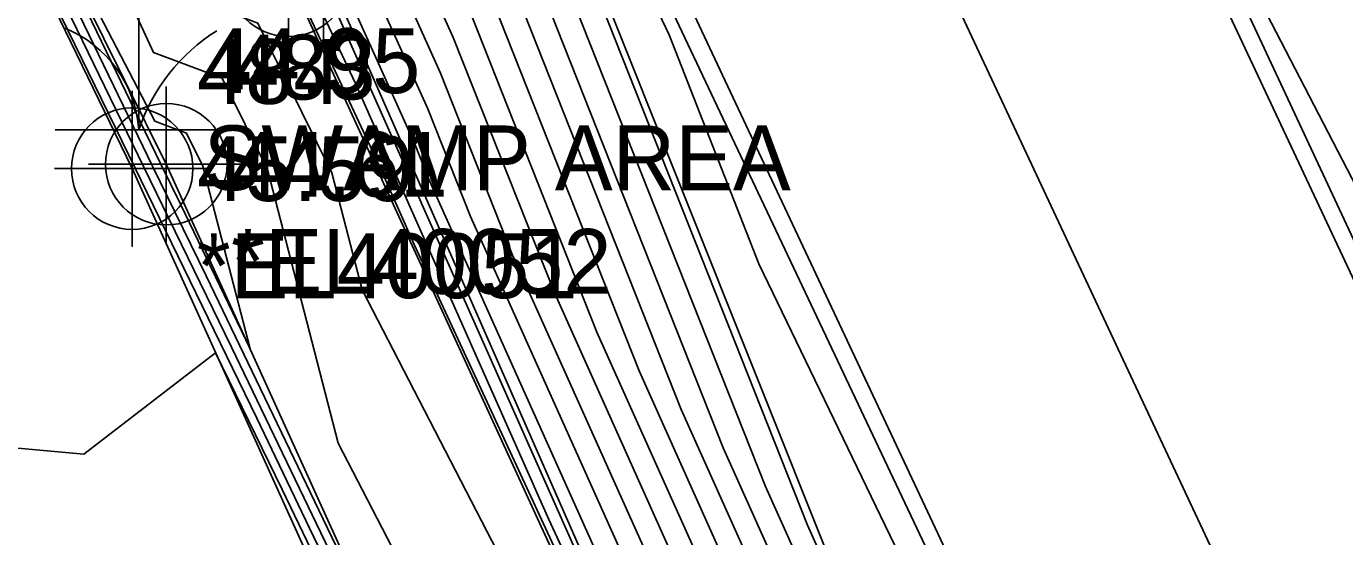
# Model space of a CAD drawing. Extents: x 2090860 to 2091277, y 159470 to 160080.
# Drawn here: x 2090993 to 2091043.8, y 159814.9 to 159834.6 of the extents above; entities that cross this region are included whole.
import ezdxf

# ---------------------------------------------------------------- set-up
doc = ezdxf.new("R2010")
doc.units = 0
for name, color, linetype in [('DTM Contours Major', 7, 'Continuous'), ('DTM Contours Minor', 7, 'Continuous'), ('Exist DTM Breakline', 7, 'Continuous'), ('Exist DTM Breakline Cogo Comment', 7, 'Continuous'), ('Exist DTM Breakline Cogo Elevation', 7, 'Continuous'), ('Exist DTM Breakline Cogo Number', 7, 'Continuous'), ('Exist DTM Breakline Cogo Point CELL', 7, 'Continuous'), ('Exist DTM Crownline', 7, 'Continuous'), ('Exist Hydro Swamp or Marsh', 7, 'Continuous'), ('Exist Hydro Swamp or Marsh Cogo Comment', 7, 'Continuous'), ('Exist Hydro Swamp or Marsh Cogo Elevation', 7, 'Continuous'), ('Exist Roads EOP', 7, 'Continuous'), ('Exist Roads EOT', 7, 'Continuous')]:
    doc.layers.add(name, color=color, linetype=linetype)

msp = doc.modelspace()

# ---------------------------------------------------------------- linework, layer by layer
at = {"layer": 'DTM Contours Major'}
for points in [[(2090991.853, 159864.196), (2090992.701, 159862.198), (2091004.114, 159836.848), (2091004.895, 159835.174), (2091007.518, 159829.269), (2091018.331, 159804.925), (2091019.741, 159801.878), (2091021.206, 159801.236), (2091025.093, 159800.189), (2091028.857, 159799.035), (2091029.349, 159799.339), (2091029.689, 159799.398), (2091044.087, 159806.371), (2091055.495, 159811.774), (2091056.395, 159812.282), (2091061.025, 159819.665), (2091060.533, 159819.671), (2091060.876, 159820.18), (2091051.784, 159837.119), (2091046.749, 159846.634), (2091042.53, 159854.466), (2091040.766, 159857.8), (2091031.335, 159877.368)], [(2091016.707, 159800.202), (2091008.385, 159811.907), (2091004.989, 159818.475), (2091002.257, 159829.041), (2091000.514, 159832.567), (2090997.856, 159833.556), (2090989.841, 159850.886), (2090987.897, 159859.839), (2090982.037, 159867.754), (2090974.898, 159876.535), (2090983.754, 159858.196), (2090986.806, 159851.928), (2090996.121, 159832.681), (2090997.829, 159829.173), (2090999.89, 159824.931), (2091004.415, 159815.535), (2091007.296, 159809.554), (2091015.202, 159792.842), (2091016.707, 159800.202)], [(2091011.396, 159839.656), (2091019.854, 159818.29), (2091022.735, 159811.87), (2091023.309, 159811.188), (2091027.181, 159801.43), (2091026.345, 159800.929), (2091025.775, 159800.251), (2091027.452, 159799.737), (2091029.469, 159800.98), (2091029.973, 159801.069), (2091031.587, 159801.932), (2091031.862, 159802.058), (2091035.483, 159803.649), (2091049.261, 159810.176)], [(2091007.255, 159838.974), (2091009.433, 159834.136), (2091013.348, 159824.247), (2091021.218, 159806.708), (2091022.786, 159804.845), (2091024.237, 159801.19), (2091023.923, 159801.002), (2091023.71, 159800.748), (2091028.154, 159799.386), (2091029.409, 159800.16), (2091030.276, 159800.311), (2091033.292, 159801.772), (2091055.189, 159812.142), (2091056.917, 159813.118), (2091059.879, 159817.842), (2091059.097, 159817.852), (2091058.757, 159817.756), (2091058.394, 159817.711), (2091056.078, 159816.651), (2091046.739, 159834.797)]]:
    msp.add_lwpolyline(points, dxfattribs=at)
at = {"layer": 'DTM Contours Minor'}
for points in [[(2090953.056, 159921.956), (2090965.045, 159895.337), (2090965.357, 159894.662), (2090965.917, 159893.402), (2090966.117, 159891.569), (2090966.399, 159891.209), (2090966.744, 159891.353), (2090970.598, 159883.648), (2090979.253, 159865.886), (2090979.998, 159864.343), (2090992.069, 159839.553), (2090993.271, 159837.069), (2090997.157, 159829.086), (2091001.847, 159819.434), (2091003.887, 159815.198), (2091014.815, 159792.51), (2091016.869, 159788.257), (2091017.431, 159786.838), (2091024.63, 159765.903)], [(2091018.49, 159801.202), (2091016.342, 159804.224), (2091005.914, 159824.395), (2091004.745, 159828.914), (2091001.892, 159834.689), (2091000.663, 159835.146), (2090996.957, 159843.159), (2090993.719, 159858.066), (2090991.183, 159864.043), (2090990.784, 159864.918), (2090986.104, 159875.843), (2090983.691, 159880.804), (2090975.225, 159897.621), (2090972.537, 159899.282), (2090971.355, 159899.978), (2090971.029, 159900.712), (2090971.838, 159903.298), (2090965.559, 159913.825)], [(2090957.425, 159912.812), (2090965.766, 159894.719), (2090966.215, 159893.707), (2090967.091, 159891.809), (2090969.426, 159886.946), (2090975.022, 159875.464), (2090981.876, 159861.269), (2090989.438, 159845.741), (2090994.696, 159834.875), (2090997.493, 159829.13), (2091000.868, 159822.182), (2091004.151, 159815.366), (2091012.999, 159796.996), (2091016.233, 159790.161), (2091018.49, 159801.202)], [(2090992.556, 159864.681), (2090993.597, 159862.423), (2091004.731, 159837.17), (2091007.961, 159829.995), (2091008.468, 159828.714), (2091020.08, 159802.837), (2091021.254, 159801.443), (2091021.996, 159801.118), (2091023.46, 159800.723), (2091028.681, 159799.123), (2091029.364, 159799.544), (2091029.836, 159799.626), (2091041.388, 159805.221), (2091055.419, 159811.866), (2091056.526, 159812.491), (2091060.739, 159819.209), (2091060.015, 159819.218), (2091060.519, 159819.967), (2091047.146, 159844.881), (2091046.348, 159846.389), (2091043.245, 159852.15), (2091040.431, 159857.259), (2091040.162, 159857.776), (2091027.446, 159884.088)], [(2090991.629, 159864.145), (2090997.549, 159850.196), (2091003.629, 159836.691), (2091005.654, 159832.353), (2091007.113, 159829.069), (2091013.126, 159815.531), (2091019.504, 159801.754), (2091020.416, 159801.354), (2091026.726, 159799.654), (2091029.032, 159798.948), (2091029.334, 159799.133), (2091029.542, 159799.17), (2091046.785, 159807.521), (2091055.572, 159811.682), (2091056.265, 159812.074), (2091061.312, 159820.121), (2091061.051, 159820.124), (2091061.233, 159820.393), (2091056.421, 159829.357), (2091047.15, 159846.879), (2091045.095, 159850.693), (2091041.19, 159858.075), (2091036.787, 159867.212)], [(2090989.86, 159846.37), (2090997.915, 159830.901), (2090999.137, 159830.446), (2090999.768, 159829.169), (2091001.594, 159822.11), (2090998.911, 159827.68), (2090998.164, 159829.216), (2090997.546, 159830.487), (2090989.86, 159846.37)], [(2091005.572, 159837.771), (2091008.452, 159831.375), (2091010.095, 159827.225), (2091020.46, 159804.127), (2091022.525, 159801.674), (2091022.764, 159801.07), (2091022.713, 159801.039), (2091022.677, 159800.997), (2091028.506, 159799.211), (2091029.379, 159799.749), (2091029.982, 159799.855), (2091038.689, 159804.071), (2091055.342, 159811.958), (2091056.656, 159812.7), (2091060.452, 159818.754), (2091059.496, 159818.766), (2091060.162, 159819.754), (2091059.308, 159821.345), (2091060.136, 159819.751), (2091059.416, 159818.737), (2091056.462, 159817.385), (2091048.56, 159832.738), (2091045.81, 159845.857)], [(2091006.414, 159838.372), (2091008.943, 159832.756), (2091011.721, 159825.736), (2091020.839, 159805.418), (2091022.655, 159803.26), (2091023.501, 159801.13), (2091023.318, 159801.02), (2091023.194, 159800.873), (2091028.33, 159799.299), (2091029.394, 159799.954), (2091030.129, 159800.083), (2091035.99, 159802.922), (2091055.266, 159812.05), (2091056.786, 159812.909), (2091060.166, 159818.298), (2091059.274, 159818.309), (2091059.116, 159818.265), (2091058.947, 159818.244), (2091056.27, 159817.018), (2091047.65, 159833.767), (2091045.241, 159845.257)], [(2091013.483, 159843.225), (2091017.769, 159834.238), (2091021.222, 159825.398), (2091030.255, 159806.684), (2091031.698, 159802.904), (2091029.981, 159801.849), (2091032.766, 159803.339), (2091033.322, 159803.593), (2091040.638, 159806.809), (2091043.341, 159808.089), (2091050.717, 159811.666), (2091051.122, 159811.969), (2091054.797, 159813.189), (2091057.794, 159814.561), (2091057.829, 159814.58), (2091057.874, 159814.652), (2091057.862, 159814.652), (2091056.242, 159814.196), (2091055.48, 159814.1), (2091054.807, 159813.737), (2091052.347, 159812.818), (2091040.46, 159835.77)], [(2091012.377, 159842.416), (2091023.107, 159815.311), (2091023.493, 159814.45), (2091023.57, 159814.359), (2091028.653, 159801.551), (2091027.555, 159800.892), (2091026.807, 159800.003), (2091027.1, 159799.913), (2091029.499, 159801.391), (2091029.662, 159801.419), (2091032.373, 159802.87), (2091032.835, 159803.082), (2091038.92, 159805.756), (2091045.314, 159808.785)], [(2091011.886, 159841.036), (2091021.481, 159816.8), (2091023.114, 159813.16), (2091023.439, 159812.773), (2091027.917, 159801.491), (2091026.95, 159800.91), (2091026.291, 159800.127), (2091027.276, 159799.825), (2091029.484, 159801.186), (2091029.818, 159801.244), (2091031.98, 159802.401), (2091032.349, 159802.57), (2091037.201, 159804.703), (2091047.287, 159809.48)], [(2091003.144, 159836.535), (2091006.413, 159829.532), (2091006.707, 159828.869), (2091007.921, 159826.138), (2091019.266, 159801.631), (2091019.626, 159801.473), (2091028.36, 159799.12), (2091029.208, 159798.86), (2091029.319, 159798.928), (2091029.396, 159798.942), (2091049.484, 159808.671), (2091055.648, 159811.59), (2091056.135, 159811.865), (2091061.598, 159820.576), (2091061.57, 159820.577), (2091061.59, 159820.607), (2091061.059, 159821.595), (2091051.606, 159839.459)], [(2091010.905, 159838.276), (2091018.227, 159819.779), (2091022.356, 159810.579), (2091023.178, 159809.602), (2091026.445, 159801.37), (2091025.739, 159800.947), (2091025.258, 159800.375), (2091027.627, 159799.65), (2091029.454, 159800.775), (2091030.129, 159800.893), (2091031.194, 159801.463), (2091031.375, 159801.546), (2091033.765, 159802.596), (2091051.234, 159810.871)], [(2091010.414, 159836.896), (2091016.601, 159821.268), (2091021.976, 159809.289), (2091023.047, 159808.016), (2091025.709, 159801.31), (2091025.134, 159800.965), (2091024.742, 159800.5), (2091027.803, 159799.562), (2091029.439, 159800.57), (2091030.285, 159800.718), (2091030.801, 159800.994), (2091030.888, 159801.034), (2091032.046, 159801.543), (2091053.208, 159811.567)], [(2091009.924, 159835.516), (2091014.974, 159822.757), (2091021.597, 159807.998), (2091022.917, 159806.431), (2091024.973, 159801.25), (2091024.529, 159800.984), (2091024.226, 159800.624), (2091027.979, 159799.474), (2091029.424, 159800.365), (2091030.422, 159800.539), (2091030.593, 159800.622), (2091055.113, 159812.234), (2091057.047, 159813.327), (2091059.593, 159817.386), (2091058.921, 159817.395), (2091058.397, 159817.247), (2091057.84, 159817.178), (2091055.886, 159816.284), (2091045.828, 159835.826)], [(2091024.559, 159765.924), (2091019.007, 159782.07), (2091016.62, 159788.099), (2091007.896, 159806.158), (2091003.623, 159815.029), (2091002.826, 159816.685), (2091000.261, 159821.963), (2090995.168, 159818.049), (2090991.625, 159818.375), (2090991.782, 159810), (2090995.432, 159804.568), (2090990, 159801.203), (2090989.571, 159800.429), (2090989.322, 159800), (2090990, 159797.747), (2090992.013, 159790), (2090990.586, 159789.414), (2090990.922, 159780), (2090990.305, 159779.695), (2090990, 159779.105)]]:
    msp.add_lwpolyline(points, dxfattribs=at)
at = {"layer": 'Exist DTM Breakline'}
for p, q in [((2090966.689, 159891.716), (2090997.039, 159829.071)), ((2090998.355, 159829.241), (2090967.299, 159891.857)), ((2091012.481, 159842.709), (2091028.915, 159801.572))]:
    msp.add_line(p, q, dxfattribs=at)
for points in [[(2091019.809, 159801.913), (2091004.418, 159836.946), (2090986.475, 159875.987), (2090967.517, 159915.028), (2090950.041, 159951.449), (2090930.695, 159992.433), (2090908.049, 160042.233)], [(2091019.111, 159801.55), (2091003.076, 159836.513), (2090986.016, 159875.809), (2090966.872, 159914.505), (2090949.073, 159951.294), (2090930.109, 159992.15), (2090906.432, 160041.549)], [(2090970.238, 159708.524), (2090995.777, 159734.72), (2091024.32, 159765.995), (2091015.838, 159787.603), (2090997.039, 159829.071)], [(2090970.603, 159708.378), (2090997.094, 159733.506), (2091024.833, 159765.843), (2091016.946, 159788.306), (2090998.355, 159829.241)]]:
    msp.add_lwpolyline(points, dxfattribs=at)
at = {"layer": 'Exist DTM Breakline Cogo Point CELL'}
for points in [[(2091004.418, 159839.946), (2091004.418, 159833.946), (2091004.418, 159836.946), (2091007.418, 159836.946), (2091001.418, 159836.946)], [(2091003.076, 159839.513), (2091003.076, 159833.513), (2091003.076, 159836.513), (2091006.076, 159836.513), (2091000.076, 159836.513)], [(2090997.039, 159832.071), (2090997.039, 159826.071), (2090997.039, 159829.071), (2091000.039, 159829.071), (2090994.039, 159829.071)], [(2090998.355, 159832.241), (2090998.355, 159826.241), (2090998.355, 159829.241), (2091001.355, 159829.241), (2090995.355, 159829.241)]]:
    msp.add_lwpolyline(points, dxfattribs=at)
for centre in [(2091003.076, 159836.513), (2090997.039, 159829.071), (2090998.355, 159829.241)]:
    msp.add_circle(centre, 2.344, dxfattribs=at)
at = {"layer": 'Exist DTM Crownline'}
msp.add_lwpolyline([(2091041.896, 159807.58), (2091022.738, 159848.476), (2091006.16, 159884.052), (2090987.202, 159924.29), (2090970.349, 159960.929), (2090951.234, 160001.943), (2090928.333, 160051.748)], dxfattribs=at)
at = {"layer": 'Exist Hydro Swamp or Marsh'}
msp.add_line((2090997.295, 159833.238), (2090997.295, 159833.238), dxfattribs=at)
msp.add_lwpolyline([(2090994.07, 159830.564), (2090997.296, 159830.564), (2090997.296, 159836.481), (2090997.296, 159830.564), (2091000.521, 159830.564)], dxfattribs=at)
for centre, radius, start, end in [((2090992.696, 159830.231), 4.612, 4.1403, 67.535), ((2091004.137, 159828.291), 7.208, 122.1274, 161.6222)]:
    msp.add_arc(centre, radius, start, end, dxfattribs=at)
at = {"layer": 'Exist Roads EOP'}
for points in [[(2091050.887, 159811.953), (2091031.567, 159853.358), (2091015.44, 159888.433), (2090996.018, 159929.558), (2090979.118, 159965.859), (2090960.144, 160006.791), (2090936.877, 160056.11)], [(2091032.873, 159803.467), (2091013.956, 159843.468), (2090996.901, 159879.939), (2090978.321, 159919.673), (2090961.239, 159956.493), (2090941.84, 159997.888), (2090918.792, 160047.284)]]:
    msp.add_lwpolyline(points, dxfattribs=at)
at = {"layer": 'Exist Roads EOT'}
for points in [[(2091050.358, 159811.619), (2091030.997, 159852.885), (2091014.318, 159887.944), (2090995.228, 159929.102), (2090978.274, 159965.509), (2090959.414, 160006.451), (2090936.296, 160055.791)], [(2091033.429, 159803.706), (2091014.624, 159843.758), (2090997.608, 159880.208), (2090978.895, 159919.952), (2090961.789, 159956.632), (2090942.516, 159998.302), (2090919.608, 160047.643)]]:
    msp.add_lwpolyline(points, dxfattribs=at)

# ---------------------------------------------------------------- texts
at = {"layer": 'Exist DTM Breakline Cogo Comment'}
for s, p in [('*EL40051', (2090999.539, 159824.071)), ('*EL40052', (2091000.855, 159824.241))]:
    msp.add_text(s, height=2.5, dxfattribs=at).set_placement(p)
at = {"layer": 'Exist DTM Breakline Cogo Elevation'}
for s, p in [('44.61', (2091000.855, 159827.991)), ('45.59', (2090999.539, 159827.821))]:
    msp.add_text(s, height=2.5, dxfattribs=at).set_placement(p)
at = {"layer": 'Exist DTM Breakline Cogo Number'}
for s, p in [('484', (2090999.539, 159831.571)), ('483', (2091000.855, 159831.741))]:
    msp.add_text(s, height=2.5, dxfattribs=at).set_placement(p)
at = {"layer": 'Exist Hydro Swamp or Marsh Cogo Comment'}
msp.add_text('SWAMP AREA', height=2.5, dxfattribs=at).set_placement((2090999.795, 159828.238))
at = {"layer": 'Exist Hydro Swamp or Marsh Cogo Elevation'}
msp.add_text('44.95', height=2.5, dxfattribs=at).set_placement((2090999.795, 159831.988))

doc.saveas('drawing.dxf')
